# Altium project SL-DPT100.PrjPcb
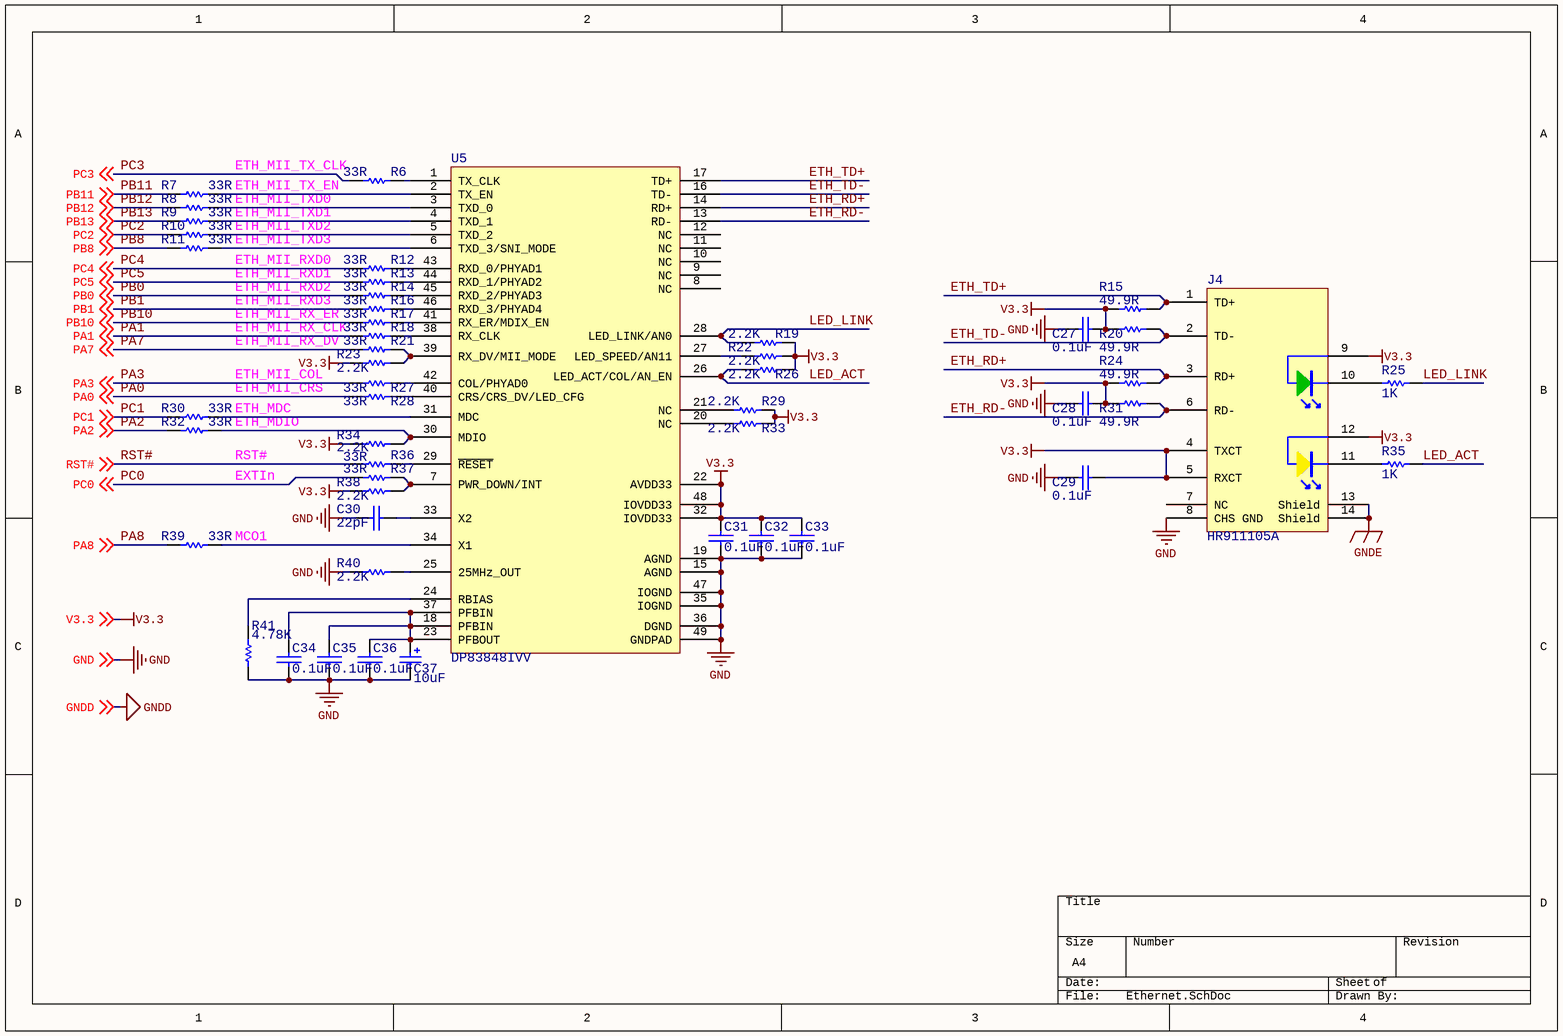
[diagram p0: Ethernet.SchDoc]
4 sheets, 170 parts. Net scope: global (net labels, ports and power ports of the same name join across sheets).
Board file: SL-DPT100.PcbDoc
Sheets:
  Ethernet.SchDoc
  MCU.SchDoc
  MCU_1.SchDoc
  Power.SchDoc

## Sheet Ethernet.SchDoc
size A4; PageSetup: Record=PageOptions|CenterHorizontal=True|CenterVertical=True|PrintScale=0.98|XCorrection=1.00|YCorrection=1.00|PrintKind=0|BorderSize=5000000|LeftOffset=0|BottomOffset=0|Orientation=2|PaperLength=1000|PaperWidth=1000|Scale=100|PaperSource=7|PrintQuality=-4|MediaType=1|DitherType=10|PaperKind=A4 210x297 ºÁÃ×|PrintScaleMode=1

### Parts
C27  0.1uF  [C1608(0603)]
C28  0.1uF  [C1608(0603)]
C29  0.1uF  [C1608(0603)]
C30  22pF  [C1608(0603)]
C31  0.1uF  [C1608(0603)]
C32  0.1uF  [C1608(0603)]
C33  0.1uF  [C1608(0603)]
C34  0.1uF  [C1608(0603)]
C35  0.1uF  [C1608(0603)]
C36  0.1uF  [C1608(0603)]
C37  10uF  [C3216(1206)]
J4  HR911105A  [RJ45-LED]
R6  33R  [R1608(0603)]
R7  33R  [R1608(0603)]
R8  33R  [R1608(0603)]
R9  33R  [R1608(0603)]
R10  33R  [R1608(0603)]
R11  33R  [R1608(0603)]
R12  33R  [R1608(0603)]
R13  33R  [R1608(0603)]
R14  33R  [R1608(0603)]
R15  49.9R  [R1608(0603)]
R16  33R  [R1608(0603)]
R17  33R  [R1608(0603)]
R18  33R  [R1608(0603)]
R19  2.2K  [R1608(0603)]
R20  49.9R  [R1608(0603)]
R21  33R  [R1608(0603)]
R22  2.2K  [R1608(0603)]
R23  2.2K  [R1608(0603)]
R24  49.9R  [R1608(0603)]
R25  1K  [R1608(0603)]
R26  2.2K  [R1608(0603)]
R27  33R  [R1608(0603)]
R28  33R  [R1608(0603)]
R29  2.2K  [R1608(0603)]
R30  33R  [R1608(0603)]
R31  49.9R  [R1608(0603)]
R32  33R  [R1608(0603)]
R33  2.2K  [R1608(0603)]
R34  2.2K  [R1608(0603)]
R35  1K  [R1608(0603)]
R36  33R  [R1608(0603)]
R37  33R  [R1608(0603)]
R38  2.2K  [R1608(0603)]
R39  33R  [R1608(0603)]
R40  2.2K  [R1608(0603)]
R41  4.78K  [R1608(0603)]
U5  DP83848IVV  [HLQFP48_M]

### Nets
GND: C27.2 C28.2 C29.2 C30.1 C31.1 C32.1 C33.1 C34.1 C35.1 C36.1 C37.2 J4.8(CHS_GND) R40.2 R41.2 U5.15(AGND) U5.19(AGND) U5.35(IOGND) U5.36(DGND) U5.47(IOGND) U5.49(GNDPAD) ; off-sheet GND
GNDE: J4.13(Shield) J4.14(Shield)
V3.3: C27.1 C28.1 C29.1 C31.2 C32.2 C33.2 J4.4(TXCT) J4.5(RXCT) J4.9 J4.12 R15.2 R19.1 R20.2 R22.1 R23.2 R24.2 R26.1 R29.1 R31.2 R33.1 R34.2 R38.2 U5.22(AVDD33) U5.32(IOVDD33) U5.48(IOVDD33) ; off-sheet V3.3
ETH_RD+: J4.3(RD+) R24.1 U5.14(RD+)
ETH_RD-: J4.6(RD-) R31.1 U5.13(RD-)
ETH_TD+: J4.1(TD+) R15.1 U5.17(TD+)
ETH_TD-: J4.2(TD-) R20.1 U5.16(TD-)
LED_ACT: R26.2 R35.2 U5.26(LED_ACT/COL/AN_EN)
LED_LINK: R19.2 R25.2 U5.28(LED_LINK/AN0)
PA0: R28.2 ; off-sheet PA0
PA1: R18.2 ; off-sheet PA1
PA2: R32.2 ; off-sheet PA2
PA3: R27.2 ; off-sheet PA3
PA7: R21.2 ; off-sheet PA7
PA8: R39.2 ; off-sheet PA8
PB0: R14.2 ; off-sheet PB0
PB1: R16.2 ; off-sheet PB1
PB8: R11.2 ; off-sheet PB8
PB10: R17.2 ; off-sheet PB10
PB11: R7.2 ; off-sheet PB11
PB12: R8.2 ; off-sheet PB12
PB13: R9.2 ; off-sheet PB13
PC0: R37.2 ; off-sheet PC0
PC1: R30.2 ; off-sheet PC1
PC2: R10.2 ; off-sheet PC2
PC3: R6.2 ; off-sheet PC3
PC4: R12.2 ; off-sheet PC4
PC5: R13.2 ; off-sheet PC5
RST#: R36.2 ; off-sheet RST#
NetC30_2: C30.2 U5.33(X2)
NetC34_2: C34.2 C35.2 C36.2 C37.1 U5.18(PFBIN) U5.23(PFBOUT) U5.37(PFBIN)
NetJ4_10: J4.10 R25.1
NetJ4_11: J4.11 R35.1
NetR6_1: R6.1 U5.1(TX_CLK)
NetR7_1: R7.1 U5.2(TX_EN)
NetR8_1: R8.1 U5.3(TXD_0)
NetR9_1: R9.1 U5.4(TXD_1)
NetR10_1: R10.1 U5.5(TXD_2)
NetR11_1: R11.1 U5.6(TXD_3/SNI_MODE)
NetR12_1: R12.1 U5.43(RXD_0/PHYAD1)
NetR13_1: R13.1 U5.44(RXD_1/PHYAD2)
NetR14_1: R14.1 U5.45(RXD_2/PHYAD3)
NetR16_1: R16.1 U5.46(RXD_3/PHYAD4)
NetR17_1: R17.1 U5.41(RX_ER/MDIX_EN)
NetR18_1: R18.1 U5.38(RX_CLK)
NetR21_1: R21.1 R23.1 U5.39(RX_DV/MII_MODE)
NetR22_2: R22.2 U5.27(LED_SPEED/AN11)
NetR27_1: R27.1 U5.42(COL/PHYAD0)
NetR28_1: R28.1 U5.40(CRS/CRS_DV/LED_CFG)
NetR29_2: R29.2 U5.21(NC)
NetR30_1: R30.1 U5.31(MDC)
NetR32_1: R32.1 R34.1 U5.30(MDIO)
NetR33_2: R33.2 U5.20(NC)
NetR36_1: R36.1 U5.29(~{RESET})
NetR37_1: R37.1 R38.1 U5.7(PWR_DOWN/INT)
NetR39_1: R39.1 U5.34(X1)
NetR40_1: R40.1 U5.25(25MHz_OUT)
NetR41_1: R41.1 U5.24(RBIAS)

Not connected (* = marked no-connect by the designer): J4 7(NC); U5 8(NC) 9(NC) 10(NC) 11(NC) 12(NC)

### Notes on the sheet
- ETH_MII_TX_CLK
- ETH_MII_TX_EN
- ETH_MII_TXD0
- ETH_MII_TXD1
- ETH_MII_TXD2
- ETH_MII_TXD3
- ETH_MII_RXD0
- ETH_MII_RXD1
- ETH_MII_RXD2
- ETH_MII_RXD3
- ETH_MII_RX_ER
- ETH_MII_RX_DV
- ETH_MII_RX_CLK
- ETH_MII_COL
- ETH_MII_CRS
- ETH_MDC
- ETH_MDIO
- RST#
- EXTIn
- (near R39) MCO1

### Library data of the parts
C27-C36 = CAP: Capacitor
C37 = Cap Pol2: Polarized Capacitor (Axial); Value: 100pF/100V
R6-R24 R26-R34 R36-R41 = Res Semi: Semiconductor Resistor; Value: 1K
R25 R35 = Res Semi: Semiconductor Resistor
U5 = DP83848CVV

## Sheet MCU.SchDoc
size A4; PageSetup: Record=PageOptions|CenterHorizontal=True|CenterVertical=True|PrintScale=0.98|XCorrection=1.00|YCorrection=1.00|PrintKind=0|BorderSize=5000000|LeftOffset=0|BottomOffset=0|Orientation=2|PaperLength=1000|PaperWidth=1000|Scale=100|PaperSource=7|PrintQuality=-4|MediaType=1|DitherType=10|PaperKind=A4 210x297 ºÁÃ×|PrintScaleMode=1
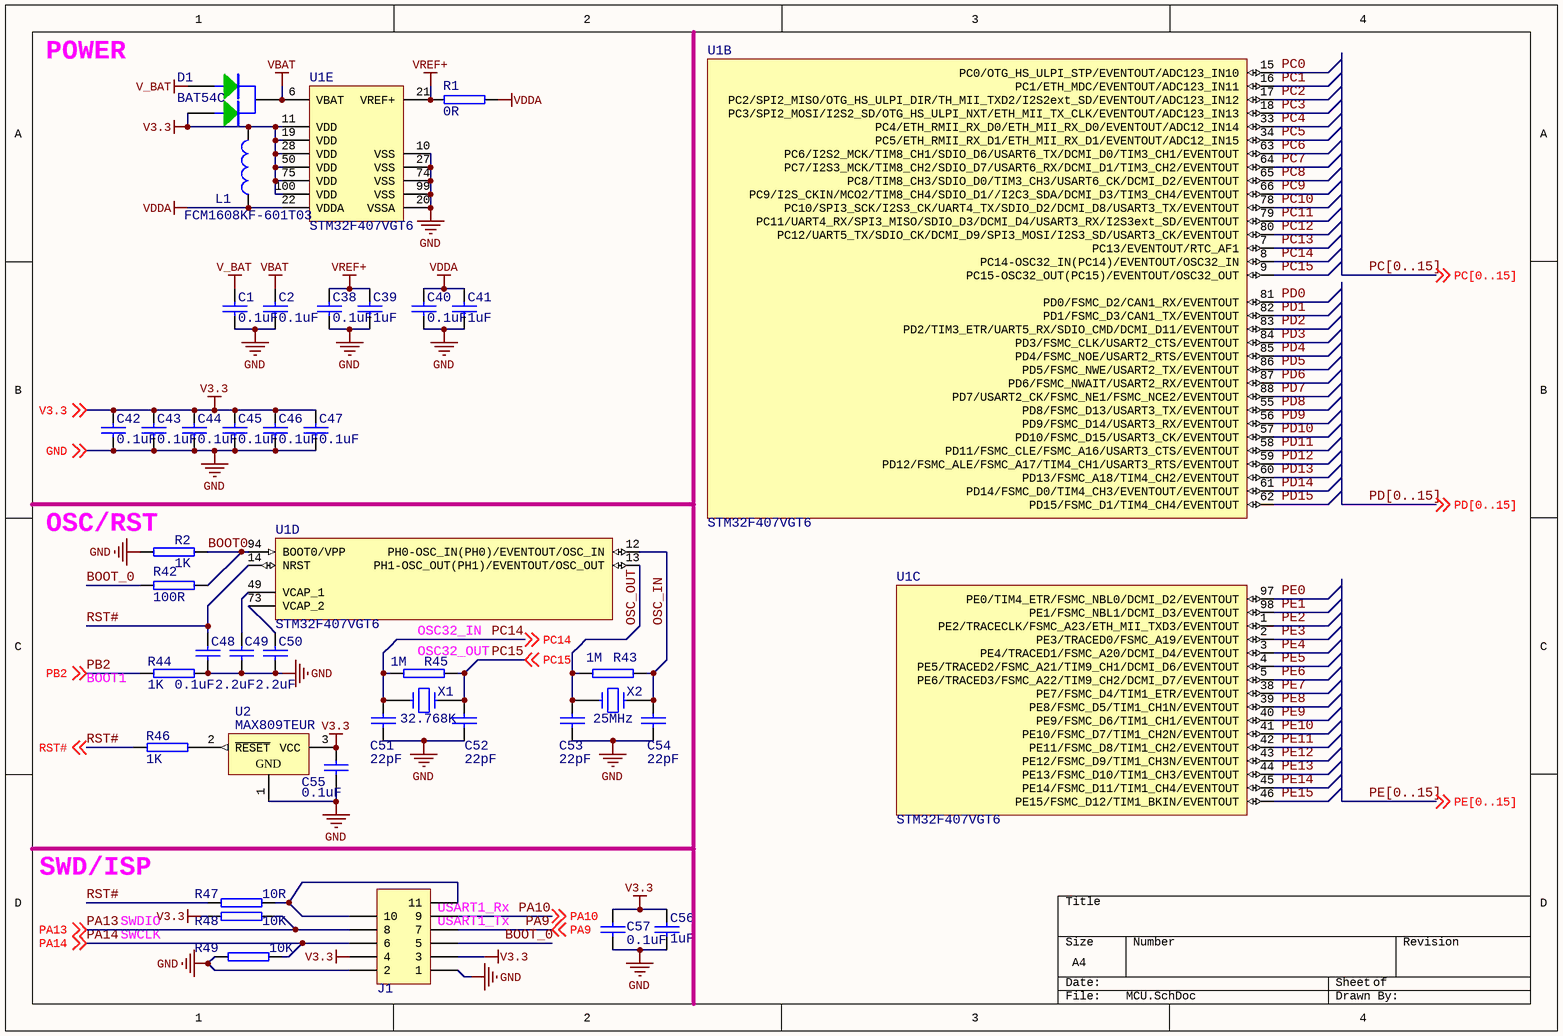
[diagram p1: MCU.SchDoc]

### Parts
C1  0.1uF  [C1608(0603)]
C2  0.1uF  [C1608(0603)]
C38  0.1uF  [C1608(0603)]
C39  1uF  [C1608(0603)]
C40  0.1uF  [C1608(0603)]
C41  1uF  [C1608(0603)]
C42  0.1uF  [C1608(0603)]
C43  0.1uF  [C1608(0603)]
C44  0.1uF  [C1608(0603)]
C45  0.1uF  [C1608(0603)]
C46  0.1uF  [C1608(0603)]
C47  0.1uF  [C1608(0603)]
C48  0.1uF  [C1608(0603)]
C49  2.2uF  [C1608(0603)]
C50  2.2uF  [C1608(0603)]
C51  22pF  [C1608(0603)]
C52  22pF  [C1608(0603)]
C53  22pF  [C1608(0603)]
C54  22pF  [C1608(0603)]
C55  0.1uF  [C1608(0603)]
C56  1uF  [C1608(0603)]
C57  0.1uF  [C1608(0603)]
D1  BAT54C  [SOT23-3_N]
J1  H2.54 6X2  [HDR2X6]  (value not drawn)
L1  FCM1608KF-601T03  [R1608(0603)]
R1  0R  [R1608(0603)]
R2  1K  [R1608(0603)]
R42  100R  [R1608(0603)]
R43  1M  [R1608(0603)]
R44  1K  [R1608(0603)]
R45  1M  [R1608(0603)]
R46  1K  [R1608(0603)]
R47  10R  [R1608(0603)]
R48  10K  [R1608(0603)]
R49  10K  [R1608(0603)]
U1  STM32F407VGT6  [TQFP100_N]  (parts B,C,D,E of 5)
U2  MAX809TEUR  [SOT23-3_N]
X1  32.768K  [FC-135]
X2  25MHz  [XTAL-3225]

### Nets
GND: C1.2 C2.2 C38.2 C39.2 C40.2 C41.2 C42.2 C43.2 C44.2 C45.2 C46.2 C47.2 C48.2 C49.2 C50.2 C51.1 C52.1 C53.1 C54.1 C55.2 C56.2 C57.1 J1.1 J1.2 R2.2 R44.1 R49.1 U1.10(VSS) U1.20(VSSA) U1.27(VSS) U1.74(VSS) U1.99(VSS) U2.1(GND) ; off-sheet GND
V3.3: C42.1 C43.1 C44.1 C45.1 C46.1 C47.1 C55.1 C56.1 C57.2 D1.2 J1.3 J1.4 L1.2 R48.1 U1.11(VDD) U1.19(VDD) U1.28(VDD) U1.50(VDD) U1.75(VDD) U1.100(VDD) U2.3(VCC) ; off-sheet V3.3
V_BAT: C1.1 D1.1
VBAT: C2.1 D1.3 U1.6(VBAT)
VDDA: C40.1 C41.1 L1.1 R1.1 U1.22(VDDA)
VREF+: C38.1 C39.1 R1.2 U1.21(VREF+)
BOOT0: R2.1 R42.2 U1.94(BOOT0/VPP)
BOOT_0: J1.5 R42.1
OSC_IN: C54.2 R43.1 U1.12(PH0-OSC_IN(PH0)/EVENTOUT/OSC_IN) X2.1
OSC_OUT: C53.2 R43.2 U1.13(PH1-OSC_OUT(PH1)/EVENTOUT/OSC_OUT) X2.3
PA9: J1.7 ; off-sheet PA9
PA10: J1.9 ; off-sheet PA10
PA13: J1.8 R48.2 ; off-sheet PA13
PA14: J1.6 R49.2 ; off-sheet PA14
PB2: R44.2 ; off-sheet PB2
PC0: U1.15(PC0/OTG_HS_ULPI_STP/EVENTOUT/ADC123_IN10)
PC1: U1.16(PC1/ETH_MDC/EVENTOUT/ADC123_IN11)
PC2: U1.17(PC2/SPI2_MISO/OTG_HS_ULPI_DIR/TH_MII_TXD2/I2S2ext_SD/EVENTOUT/ADC123_IN12)
PC3: U1.18(PC3/SPI2_MOSI/I2S2_SD/OTG_HS_ULPI_NXT/ETH_MII_TX_CLK/EVENTOUT/ADC123_IN13)
PC4: U1.33(PC4/ETH_RMII_RX_D0/ETH_MII_RX_D0/EVENTOUT/ADC12_IN14)
PC5: U1.34(PC5/ETH_RMII_RX_D1/ETH_MII_RX_D1/EVENTOUT/ADC12_IN15)
PC6: U1.63(PC6/I2S2_MCK/TIM8_CH1/SDIO_D6/USART6_TX/DCMI_D0/TIM3_CH1/EVENTOUT)
PC7: U1.64(PC7/I2S3_MCK/TIM8_CH2/SDIO_D7/USART6_RX/DCMI_D1/TIM3_CH2/EVENTOUT)
PC8: U1.65(PC8/TIM8_CH3/SDIO_D0/TIM3_CH3/USART6_CK/DCMI_D2/EVENTOUT)
PC9: U1.66(PC9/I2S_CKIN/MCO2/TIM8_CH4/SDIO_D1//I2C3_SDA/DCMI_D3/TIM3_CH4/EVENTOUT)
PC10: U1.78(PC10/SPI3_SCK/I2S3_CK/UART4_TX/SDIO_D2/DCMI_D8/USART3_TX/EVENTOUT)
PC11: U1.79(PC11/UART4_RX/SPI3_MISO/SDIO_D3/DCMI_D4/USART3_RX/I2S3ext_SD/EVENTOUT)
PC12: U1.80(PC12/UART5_TX/SDIO_CK/DCMI_D9/SPI3_MOSI/I2S3_SD/USART3_CK/EVENTOUT)
PC13: U1.7(PC13/EVENTOUT/RTC_AF1)
PC14: C51.2 R45.2 U1.8(PC14-OSC32_IN(PC14)/EVENTOUT/OSC32_IN) X1.2 ; off-sheet PC14
PC15: C52.2 R45.1 U1.9(PC15-OSC32_OUT(PC15)/EVENTOUT/OSC32_OUT) X1.1 ; off-sheet PC15
PD0: U1.81(PD0/FSMC_D2/CAN1_RX/EVENTOUT)
PD1: U1.82(PD1/FSMC_D3/CAN1_TX/EVENTOUT)
PD2: U1.83(PD2/TIM3_ETR/UART5_RX/SDIO_CMD/DCMI_D11/EVENTOUT)
PD3: U1.84(PD3/FSMC_CLK/USART2_CTS/EVENTOUT)
PD4: U1.85(PD4/FSMC_NOE/USART2_RTS/EVENTOUT)
PD5: U1.86(PD5/FSMC_NWE/USART2_TX/EVENTOUT)
PD6: U1.87(PD6/FSMC_NWAIT/USART2_RX/EVENTOUT)
PD7: U1.88(PD7/USART2_CK/FSMC_NE1/FSMC_NCE2/EVENTOUT)
PD8: U1.55(PD8/FSMC_D13/USART3_TX/EVENTOUT)
PD9: U1.56(PD9/FSMC_D14/USART3_RX/EVENTOUT)
PD10: U1.57(PD10/FSMC_D15/USART3_CK/EVENTOUT)
PD11: U1.58(PD11/FSMC_CLE/FSMC_A16/USART3_CTS/EVENTOUT)
PD12: U1.59(PD12/FSMC_ALE/FSMC_A17/TIM4_CH1/USART3_RTS/EVENTOUT)
PD13: U1.60(PD13/FSMC_A18/TIM4_CH2/EVENTOUT)
PD14: U1.61(PD14/FSMC_D0/TIM4_CH3/EVENTOUT/EVENTOUT)
PD15: U1.62(PD15/FSMC_D1/TIM4_CH4/EVENTOUT)
PE0: U1.97(PE0/TIM4_ETR/FSMC_NBL0/DCMI_D2/EVENTOUT)
PE1: U1.98(PE1/FSMC_NBL1/DCMI_D3/EVENTOUT)
PE2: U1.1(PE2/TRACECLK/FSMC_A23/ETH_MII_TXD3/EVENTOUT)
PE3: U1.2(PE3/TRACED0/FSMC_A19/EVENTOUT)
PE4: U1.3(PE4/TRACED1/FSMC_A20/DCMI_D4/EVENTOUT)
PE5: U1.4(PE5/TRACED2/FSMC_A21/TIM9_CH1/DCMI_D6/EVENTOUT)
PE6: U1.5(PE6/TRACED3/FSMC_A22/TIM9_CH2/DCMI_D7/EVENTOUT)
PE7: U1.38(PE7/FSMC_D4/TIM1_ETR/EVENTOUT)
PE8: U1.39(PE8/FSMC_D5/TIM1_CH1N/EVENTOUT)
PE9: U1.40(PE9/FSMC_D6/TIM1_CH1/EVENTOUT)
PE10: U1.41(PE10/FSMC_D7/TIM1_CH2N/EVENTOUT)
PE11: U1.42(PE11/FSMC_D8/TIM1_CH2/EVENTOUT)
PE12: U1.43(PE12/FSMC_D9/TIM1_CH3N/EVENTOUT)
PE13: U1.44(PE13/FSMC_D10/TIM1_CH3/EVENTOUT)
PE14: U1.45(PE14/FSMC_D11/TIM1_CH4/EVENTOUT)
PE15: U1.46(PE15/FSMC_D12/TIM1_BKIN/EVENTOUT)
RST#: C48.1 R46.1 R47.2 U1.14(NRST) ; off-sheet RST#
NetC49_1: C49.1 U1.49(VCAP_1)
NetC50_1: C50.1 U1.73(VCAP_2)
NetJ1_10: J1.10 J1.11 R47.1
NetR46_2: R46.2 U2.2(~{RESET})

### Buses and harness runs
bus PC[0..15]
bus PD[0..15]
bus PE[0..15]

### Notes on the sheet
- POWER
- (near R2) OSC/RST
- (near U1) OSC32_IN
- (near R45) OSC32_OUT
- (near R44) BOOT1
- SWD/ISP
- SWDIO
- (near J1) USART1_Tx
- (near J1) USART1_Rx
- SWCLK

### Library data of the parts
C1 C2 C38-C57 = CAP: Capacitor
J1 = Header 6X2: Header, 6-Pin, Dual row
L1 = Inductor: Code_IEC: 1005; Value: 10mH
R1 R2 R42-R49 = R
U1 = STM32F407VGT6: ARM Cortex-M4 32b MCU+FPU, 210DMIP, 1024 kB Flash, 192+4 kB RAM, Camera, 82 I/Os, 100-pin LQFP, -40 to +85°C, Tray; Internal RAM: 192kB; Operating Frequency (Processor Speed): 168MHz; A/D Converter: 16x12-bit; D/A Converter: 2x12-bit; 16-bit Timers (IC/OC/PWM): 12x16-bit(24/24/30); 32-bit Timer (IC/OC/PWM): 2x32-bit (8/8/8); Other Timer Functions: 2xWDG, RTC, 24-bit down counter; Serial Interface: 3xSPI/2xI2S/2xI2C/3xUSART(IrDa, ISO7816)/3xUART/2xUSB OTG FS/HS, 2xCAN/Ethernet MAC10/100, SDIO
U2 = MAX6520EUR-T: 3-Terminal, 1.2V Voltage Reference
X1 X2 = CRYSTAL

## Sheet MCU_1.SchDoc
size A4; PageSetup: Record=PageOptions|CenterHorizontal=True|CenterVertical=True|PrintScale=0.98|XCorrection=1.00|YCorrection=1.00|PrintKind=0|BorderSize=5000000|LeftOffset=0|BottomOffset=0|Orientation=2|PaperLength=1000|PaperWidth=1000|Scale=100|PaperSource=7|PrintQuality=-4|MediaType=1|DitherType=10|PaperKind=A4 210x297 ºÁÃ×|PrintScaleMode=1
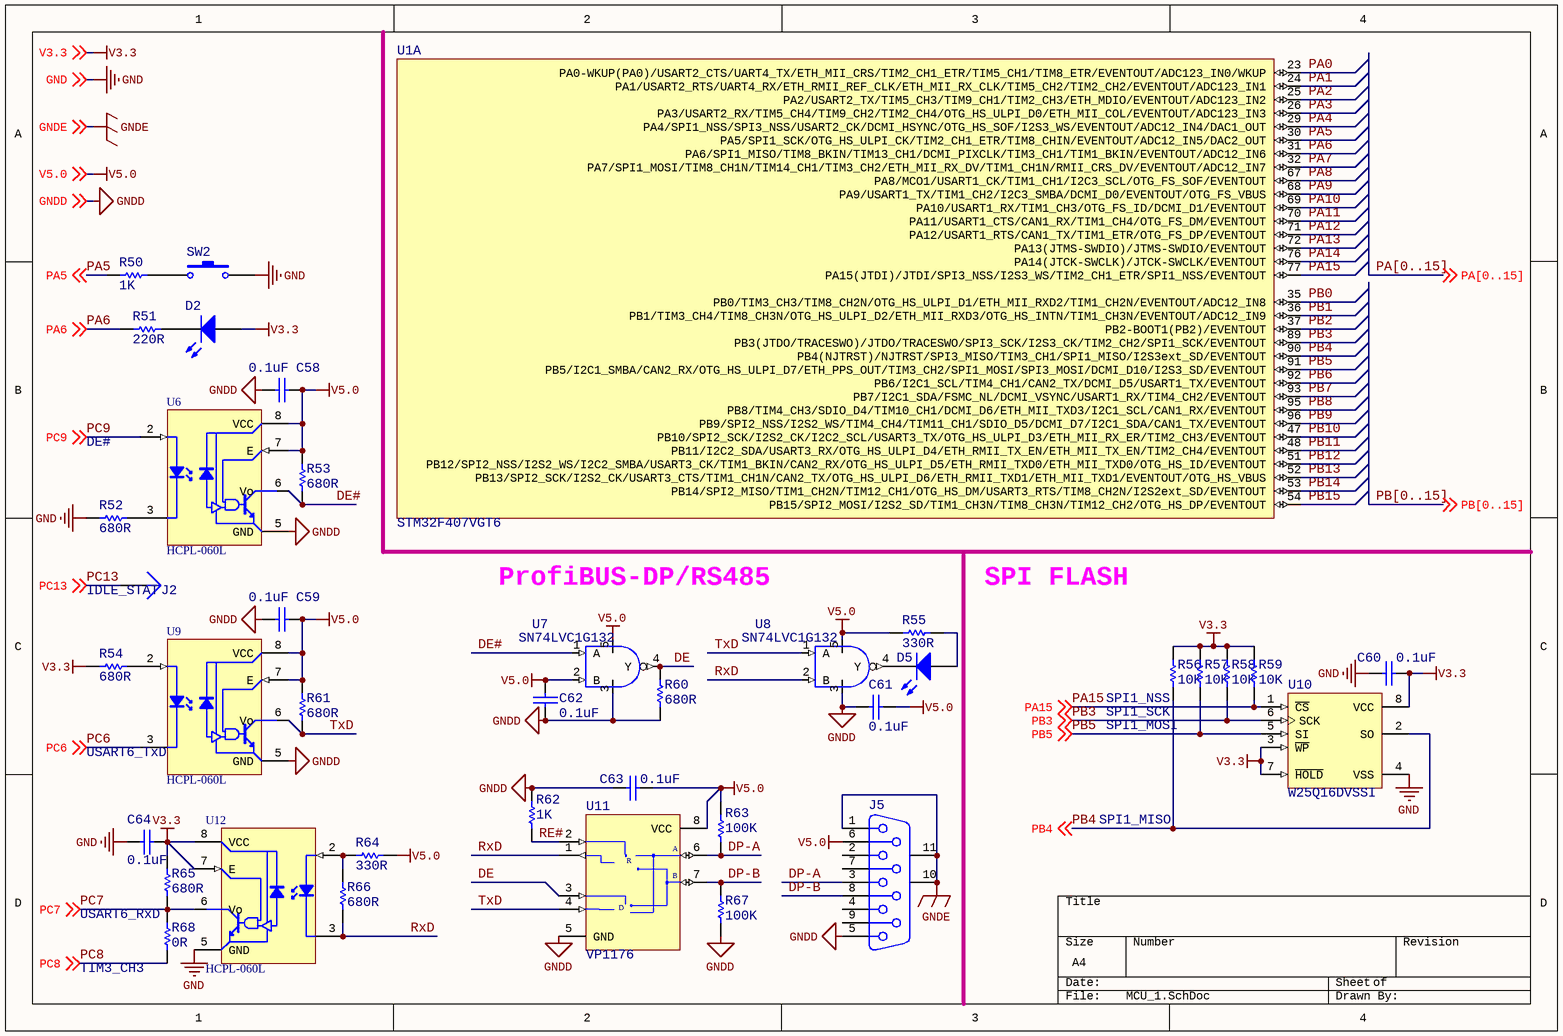
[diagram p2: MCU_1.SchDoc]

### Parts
C58  0.1uF  [C1608(0603)]
C59  0.1uF  [C1608(0603)]
C60  0.1uF  [C1608(0603)]
C61  0.1uF  [C1608(0603)]
C62  0.1uF  [C1608(0603)]
C63  0.1uF  [C1608(0603)]
C64  0.1uF  [C1608(0603)]
D2  LED0  [LED-1]  (value not drawn)
D5  LED0  [LED-1]  (value not drawn)
J2  Plug  [PIN1]  (value not drawn)
J5  D Connector 9  [DB9F]  (value not drawn)
R50  1K  [R1608(0603)]
R51  220R  [R1608(0603)]
R52  680R  [R1608(0603)]
R53  680R  [R1608(0603)]
R54  680R  [R1608(0603)]
R55  330R  [R1608(0603)]
R56  10K  [R1608(0603)]
R57  10K  [R1608(0603)]
R58  10K  [R1608(0603)]
R59  10K  [R1608(0603)]
R60  680R  [R1608(0603)]
R61  680R  [R1608(0603)]
R62  1K  [R1608(0603)]
R63  100K  [R1608(0603)]
R64  330R  [R1608(0603)]
R65  680R  [R1608(0603)]
R66  680R  [R1608(0603)]
R67  100K  [R1608(0603)]
R68  0R  [R1608(0603)]
SW2  SW-PB  [Key2x4]  (value not drawn)
U1  STM32F407VGT6  [TQFP100_N]  (part A of 5)
U6  HCPL-060L  [SO8_M]
U7  SN74LVC1G132  [SOT23-5_N]
U8  SN74LVC1G132  [SOT23-5_N]
U9  HCPL-060L  [SO8_M]
U10  W25Q16DVSSI  [SOIC8_M]
U11  VP1176  [SO8_M]
U12  HCPL-060L  [SO8_M]

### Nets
GND: C60.2 C64.2 R52.1 SW2.2 U10.4(VSS) U12.5(GND) ; off-sheet GND
GNDD: C58.2 C59.2 C61.1 C62.2 C63.2 J5.5 R60.1 R62.2 R67.1 U6.5(GND) U7.3(GND) U8.3(GND) U9.5(GND) U11.5(GND) ; off-sheet GNDD
GNDE: J5.1 J5.10(MH1) J5.11(MH2) ; off-sheet GNDE
V3.3: C60.1 C64.1 D2.1(A) R54.1 R56.2 R57.2 R58.2 R59.2 R65.2 U10.3(~{WP}) U10.7(~{HOLD}) U10.8(VCC) U12.7(E) U12.8(VCC) ; off-sheet V3.3
V5.0: C58.1 C59.1 C61.2 C62.1 C63.1 J5.6 R53.2 R55.1 R61.2 R63.2 R64.2 U6.7(E) U6.8(VCC) U7.2(B) U7.5(VCC) U8.5(VCC) U9.7(E) U9.8(VCC) U11.8(VCC) ; off-sheet V5.0
DE: R60.2 U7.4(Y) U11.3(DE)
DE#: R53.1 U6.6(Vo) U7.1(A)
DP-A: J5.3 R63.1 U11.6(A)
DP-B: J5.8 R67.2 U11.7(B)
PA0: U1.23(PA0-WKUP(PA0)/USART2_CTS/UART4_TX/ETH_MII_CRS/TIM2_CH1_ETR/TIM5_CH1/TIM8_ETR/EVENTOUT/ADC123_IN0/WKUP)
PA1: U1.24(PA1/USART2_RTS/UART4_RX/ETH_RMII_REF_CLK/ETH_MII_RX_CLK/TIM5_CH2/TIM2_CH2/EVENTOUT/ADC123_IN1)
PA2: U1.25(PA2/USART2_TX/TIM5_CH3/TIM9_CH1/TIM2_CH3/ETH_MDIO/EVENTOUT/ADC123_IN2)
PA3: U1.26(PA3/USART2_RX/TIM5_CH4/TIM9_CH2/TIM2_CH4/OTG_HS_ULPI_D0/ETH_MII_COL/EVENTOUT/ADC123_IN3)
PA4: U1.29(PA4/SPI1_NSS/SPI3_NSS/USART2_CK/DCMI_HSYNC/OTG_HS_SOF/I2S3_WS/EVENTOUT/ADC12_IN4/DAC1_OUT)
PA5: R50.1 U1.30(PA5/SPI1_SCK/OTG_HS_ULPI_CK/TIM2_CH1_ETR/TIM8_CHIN/EVENTOUT/ADC12_IN5/DAC2_OUT) ; off-sheet PA5
PA6: R51.1 U1.31(PA6/SPI1_MISO/TIM8_BKIN/TIM13_CH1/DCMI_PIXCLK/TIM3_CH1/TIM1_BKIN/EVENTOUT/ADC12_IN6) ; off-sheet PA6
PA7: U1.32(PA7/SPI1_MOSI/TIM8_CH1N/TIM14_CH1/TIM3_CH2/ETH_MII_RX_DV/TIM1_CH1N/RMII_CRS_DV/EVENTOUT/ADC12_IN7)
PA8: U1.67(PA8/MCO1/USART1_CK/TIM1_CH1/I2C3_SCL/OTG_FS_SOF/EVENTOUT)
PA9: U1.68(PA9/USART1_TX/TIM1_CH2/I2C3_SMBA/DCMI_D0/EVENTOUT/OTG_FS_VBUS)
PA10: U1.69(PA10/USART1_RX/TIM1_CH3/OTG_FS_ID/DCMI_D1/EVENTOUT)
PA11: U1.70(PA11/USART1_CTS/CAN1_RX/TIM1_CH4/OTG_FS_DM/EVENTOUT)
PA12: U1.71(PA12/USART1_RTS/CAN1_TX/TIM1_ETR/OTG_FS_DP/EVENTOUT)
PA13: U1.72(PA13(JTMS-SWDIO)/JTMS-SWDIO/EVENTOUT)
PA14: U1.76(PA14(JTCK-SWCLK)/JTCK-SWCLK/EVENTOUT)
PA15: R59.1 U1.77(PA15(JTDI)/JTDI/SPI3_NSS/I2S3_WS/TIM2_CH1_ETR/SPI1_NSS/EVENTOUT) U10.1(~{CS}) ; off-sheet PA15
PB0: U1.35(PB0/TIM3_CH3/TIM8_CH2N/OTG_HS_ULPI_D1/ETH_MII_RXD2/TIM1_CH2N/EVENTOUT/ADC12_IN8)
PB1: U1.36(PB1/TIM3_CH4/TIM8_CH3N/OTG_HS_ULPI_D2/ETH_MII_RXD3/OTG_HS_INTN/TIM1_CH3N/EVENTOUT/ADC12_IN9)
PB2: U1.37(PB2-BOOT1(PB2)/EVENTOUT)
PB3: R58.1 U1.89(PB3(JTDO/TRACESWO)/JTDO/TRACESWO/SPI3_SCK/I2S3_CK/TIM2_CH2/SPI1_SCK/EVENTOUT) U10.6(SCK) ; off-sheet PB3
PB4: R56.1 U1.90(PB4(NJTRST)/NJTRST/SPI3_MISO/TIM3_CH1/SPI1_MISO/I2S3ext_SD/EVENTOUT) U10.2(SO) ; off-sheet PB4
PB5: R57.1 U1.91(PB5/I2C1_SMBA/CAN2_RX/OTG_HS_ULPI_D7/ETH_PPS_OUT/TIM3_CH2/SPI1_MOSI/SPI3_MOSI/DCMI_D10/I2S3_SD/EVENTOUT) U10.5(SI) ; off-sheet PB5
PB6: U1.92(PB6/I2C1_SCL/TIM4_CH1/CAN2_TX/DCMI_D5/USART1_TX/EVENTOUT)
PB7: U1.93(PB7/I2C1_SDA/FSMC_NL/DCMI_VSYNC/USART1_RX/TIM4_CH2/EVENTOUT)
PB8: U1.95(PB8/TIM4_CH3/SDIO_D4/TIM10_CH1/DCMI_D6/ETH_MII_TXD3/I2C1_SCL/CAN1_RX/EVENTOUT)
PB9: U1.96(PB9/SPI2_NSS/I2S2_WS/TIM4_CH4/TIM11_CH1/SDIO_D5/DCMI_D7/I2C1_SDA/CAN1_TX/EVENTOUT)
PB10: U1.47(PB10/SPI2_SCK/I2S2_CK/I2C2_SCL/USART3_TX/OTG_HS_ULPI_D3/ETH_MII_RX_ER/TIM2_CH3/EVENTOUT)
PB11: U1.48(PB11/I2C2_SDA/USART3_RX/OTG_HS_ULPI_D4/ETH_RMII_TX_EN/ETH_MII_TX_EN/TIM2_CH4/EVENTOUT)
PB12: U1.51(PB12/SPI2_NSS/I2S2_WS/I2C2_SMBA/USART3_CK/TIM1_BKIN/CAN2_RX/OTG_HS_ULPI_D5/ETH_RMII_TXD0/ETH_MII_TXD0/OTG_HS_ID/EVENTOUT)
PB13: U1.52(PB13/SPI2_SCK/I2S2_CK/USART3_CTS/TIM1_CH1N/CAN2_TX/OTG_HS_ULPI_D6/ETH_RMII_TXD1/ETH_MII_TXD1/EVENTOUT/OTG_HS_VBUS)
PB14: U1.53(PB14/SPI2_MISO/TIM1_CH2N/TIM12_CH1/OTG_HS_DM/USART3_RTS/TIM8_CH2N/I2S2ext_SD/EVENTOUT)
PB15: U1.54(PB15/SPI2_MOSI/I2S2_SD/TIM1_CH3N/TIM8_CH3N/TIM12_CH2/OTG_HS_DP/EVENTOUT)
PC6: U9.3(-) ; off-sheet PC6
PC7: R65.1 R68.2 U12.6(Vo) ; off-sheet PC7
PC8: R68.1 ; off-sheet PC8
PC9: U6.2(+) ; off-sheet PC9
PC13: J2.1 ; off-sheet PC13
RE#: R62.1 U11.2(~{RE})
RxD: R66.1 U8.2(B) U11.1(RO) U12.3(-)
TxD: R61.1 U8.1(A) U9.6(Vo) U11.4(DI)
NetD2_2: D2.2(K) R51.2
NetD5_1: D5.1(A) R55.2
NetD5_2: D5.2(K) U8.4(Y)
NetR50_2: R50.2 SW2.1
NetR52_2: R52.2 U6.3(-)
NetR54_2: R54.2 U9.2(+)
NetR64_1: R64.1 R66.2 U12.2(+)

Not connected (* = marked no-connect by the designer): J5 2 4 7 9

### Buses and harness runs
bus PA[0..15]
bus PB[0..15]

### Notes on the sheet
- DE#
- (near J2) IDLE_STAT
- ProfiBUS-DP/RS485
- SPI FLASH
- (near R56) SPI1_NSS
- (near R56) SPI1_SCK
- (near U9) USART6_TxD
- SPI1_MOSI
- SPI1_MISO
- USART6_RxD
- (near R68) TIM3_CH3

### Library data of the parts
C58-C64 = CAP: Capacitor
D2 D5 = LED0: Typical INFRARED GaAs LED
J5 = D Connector 9: Receptacle Assembly, 9 Position, Right Angle; PackageDocument: O; Positions: 9
R50 R62 = Res Semi: Semiconductor Resistor
R51-R61 R63-R68 = Res Semi: Semiconductor Resistor; Value: 1K
SW2 = SW-PB: Switch
U1 = STM32F407VGT6: as U1 on sheet MCU
U6 U9 U12 = HCPL-060
U10 = 25AA640A-I/SN: 64K SPI Bus Serial EEPROM, 8-Pin SOIC, Industrial Temperature
U11 = MAX485ESA: Low-Power, Slew-Rate-Limited RS-485/RS-422 Transceiver

## Sheet Power.SchDoc
size A4; PageSetup: Record=PageOptions嶤enterHorizontal=True嶤enterVertical=True嶱rintScale=0.98嶺Correction=1.00嶻Correction=1.00嶱rintKind=0嶣orderSize=5000000嶭eftOffset=0嶣ottomOffset=0嶰rientation=2嶱aperLength=1000嶱aperWidth=1000嶴cale=100嶱aperSource=7嶱rintQuality=-4嶮ediaType=1嶥itherType=10嶱aperKind=信纸嶱rintScaleMode=1
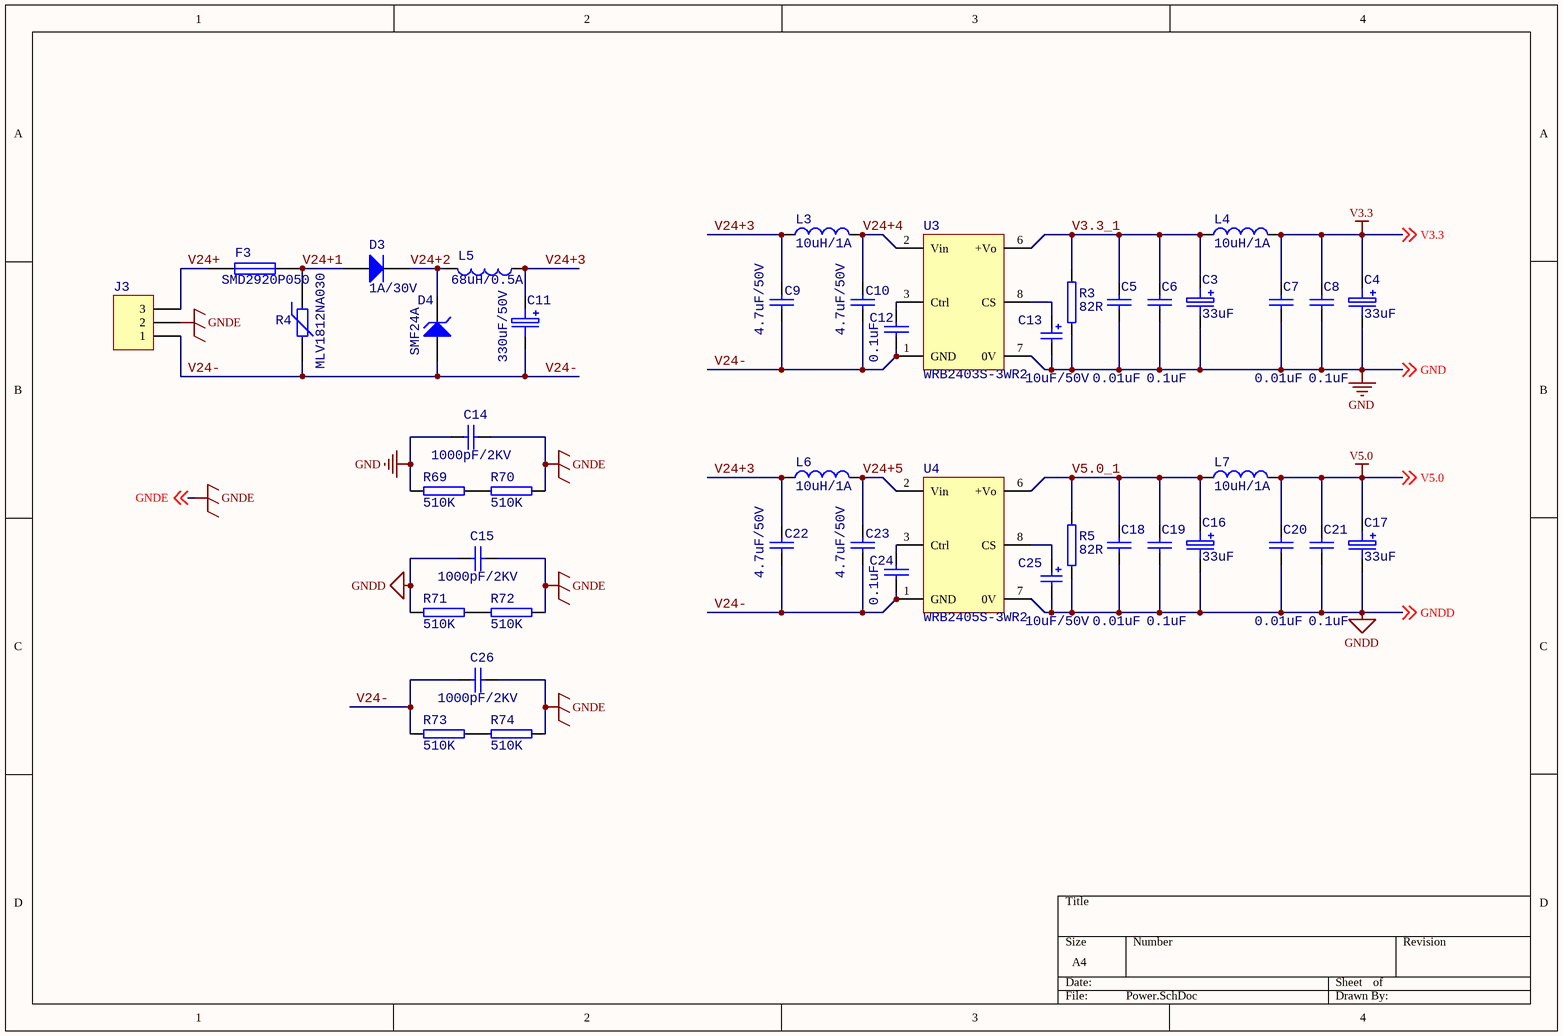
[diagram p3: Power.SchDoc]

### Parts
C3  33uF  [C3528(B)]
C4  33uF  [C3528(B)]
C5  0.01uF  [C1608(0603)]
C6  0.1uF  [C1608(0603)]
C7  0.01uF  [C1608(0603)]
C8  0.1uF  [C1608(0603)]
C9  4.7uF/50V  [C2012(0805)]
C10  4.7uF/50V  [C2012(0805)]
C11  330uF/50V  [CAPMP10X120]
C12  0.1uF  [C1608(0603)]
C13  10uF/50V  [C3216(1206)]
C14  1000pF/2KV  [C3216(1206)]
C15  1000pF/2KV  [C3216(1206)]
C16  33uF  [C3528(B)]
C17  33uF  [C3528(B)]
C18  0.01uF  [C1608(0603)]
C19  0.1uF  [C1608(0603)]
C20  0.01uF  [C1608(0603)]
C21  0.1uF  [C1608(0603)]
C22  4.7uF/50V  [C2012(0805)]
C23  4.7uF/50V  [C2012(0805)]
C24  0.1uF  [C1608(0603)]
C25  10uF/50V  [C3216(1206)]
C26  1000pF/2KV  [C3216(1206)]
D3  1A/30V  [SOD323]
D4  SMF24A  [SOD123]
F3  SMD2920P050  [R7555(2920)]
J3  Header 3  [MKDSO2.5 HV/3R-7.5]  (value not drawn)
L3  10uH/1A  [L4040]
L4  10uH/1A  [L4040]
L5  68uH/0.5A  [L4040]
L6  10uH/1A  [L4040]
L7  10uH/1A  [L4040]
R3  82R  [R3216(1206)]
R4  MLV1812NA030  [R4532(1812)]
R5  82R  [R3216(1206)]
R69  510K  [TGR]
R70  510K  [TGR]
R71  510K  [TGR]
R72  510K  [TGR]
R73  510K  [TGR]
R74  510K  [TGR]
U3  WRB2403S-3WR2  [SIP8]
U4  WRB2405S-3WR2  [SIP8]

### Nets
GND: C3.2 C4.2 C5.1 C6.1 C7.1 C8.1 C13.2 C14.1 R3.2 R69.1 U3.7(0V) ; off-sheet GND
GNDD: C15.1 C16.2 C17.2 C18.1 C19.1 C20.1 C21.1 C25.2 R5.2 R71.1 U4.7(0V) ; off-sheet GNDD
GNDE: C14.2 C15.2 C26.2 J3.2 R70.2 R72.2 R74.2 ; off-sheet GNDE
V3.3: C4.1 C7.2 C8.2 L4.2 ; off-sheet V3.3
V5.0: C17.1 C20.2 C21.2 L7.2 ; off-sheet V5.0
V3.3_1: C3.1 C5.2 C6.2 L4.1 R3.1 U3.6(+Vo)
V5.0_1: C16.1 C18.2 C19.2 L7.1 R5.1 U4.6(+Vo)
V24+: F3.1 J3.3
V24+1: D3.1(A) F3.2 R4.1
V24+2: D3.2(K) D4.2(K) L5.2
V24+3: C9.2 C11.1 C22.2 L3.1 L5.1 L6.1
V24+4: C10.2 L3.2 U3.2(Vin)
V24+5: C23.2 L6.2 U4.2(Vin)
V24-: C9.1 C10.1 C11.2 C12.2 C22.1 C23.1 C24.2 C26.1 D4.1(A) J3.1 R4.2 R73.1 U3.1(GND) U4.1(GND)
NetC12_1: C12.1 U3.3(Ctrl)
NetC13_1: C13.1 U3.8(CS)
NetC24_1: C24.1 U4.3(Ctrl)
NetC25_1: C25.1 U4.8(CS)
NetR69_2: R69.2 R70.1
NetR71_2: R71.2 R72.1
NetR73_2: R73.2 R74.1

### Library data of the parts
C3 C4 C11 C16 C17 = CAPACITOR POL: CA45-?V?uF ABCD 16V10UF[A型3210]16V22UF(B型1210) 16V47UF(C型1812)
C5-C10 C12 C14 C15 C18-C24 C26 = CAP: Capacitor
C13 C25 = Cap Pol2: as C37 on sheet Ethernet
D3 = Diode: Default Diode
D4 = D Zener: Zener Diode
F3 = FUSE1: Fuse
J3 = Header 3: Header, 3-Pin
L3 L4 L6 L7 = Inductor: Code_IEC: 1005; Value: ABRACON
L5 = Inductor: Code_IEC: 1005; Value: SRN4018-680M/CD32-680K
R3 R5 R69-R74 = R
R4 = Res Varistor: Varistor (Voltage-Sensitive Resistor)
U3 U4 = WRA_S-1WR2

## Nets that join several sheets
GND: Ethernet (20 pins), MCU (33 pins), MCU_1 (6 pins), Power (11 pins)
GNDD: MCU_1 (14 pins), Power (11 pins)
GNDE: Ethernet (J4.13 J4.14), MCU_1 (J5.1 J5.10 J5.11), Power (7 pins)
V3.3: Ethernet (25 pins), MCU (21 pins), MCU_1 (14 pins), Power (C4.1 C7.2 C8.2 L4.2)
V5.0: MCU_1 (19 pins), Power (C17.1 C20.2 C21.2 L7.2)
PA0: Ethernet (R28.2), MCU_1 (U1.23)
PA1: Ethernet (R18.2), MCU_1 (U1.24)
PA2: Ethernet (R32.2), MCU_1 (U1.25)
PA3: Ethernet (R27.2), MCU_1 (U1.26)
PA7: Ethernet (R21.2), MCU_1 (U1.32)
PA8: Ethernet (R39.2), MCU_1 (U1.67)
PA9: MCU (J1.7), MCU_1 (U1.68)
PA10: MCU (J1.9), MCU_1 (U1.69)
PA13: MCU (J1.8 R48.2), MCU_1 (U1.72)
PA14: MCU (J1.6 R49.2), MCU_1 (U1.76)
PB0: Ethernet (R14.2), MCU_1 (U1.35)
PB1: Ethernet (R16.2), MCU_1 (U1.36)
PB2: MCU (R44.2), MCU_1 (U1.37)
PB8: Ethernet (R11.2), MCU_1 (U1.95)
PB10: Ethernet (R17.2), MCU_1 (U1.47)
PB11: Ethernet (R7.2), MCU_1 (U1.48)
PB12: Ethernet (R8.2), MCU_1 (U1.51)
PB13: Ethernet (R9.2), MCU_1 (U1.52)
PC0: Ethernet (R37.2), MCU (U1.15)
PC1: Ethernet (R30.2), MCU (U1.16)
PC2: Ethernet (R10.2), MCU (U1.17)
PC3: Ethernet (R6.2), MCU (U1.18)
PC4: Ethernet (R12.2), MCU (U1.33)
PC5: Ethernet (R13.2), MCU (U1.34)
PC6: MCU (U1.63), MCU_1 (U9.3)
PC7: MCU (U1.64), MCU_1 (R65.1 R68.2 U12.6)
PC8: MCU (U1.65), MCU_1 (R68.1)
PC9: MCU (U1.66), MCU_1 (U6.2)
PC13: MCU (U1.7), MCU_1 (J2.1)
RST#: Ethernet (R36.2), MCU (C48.1 R46.1 R47.2 U1.14)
